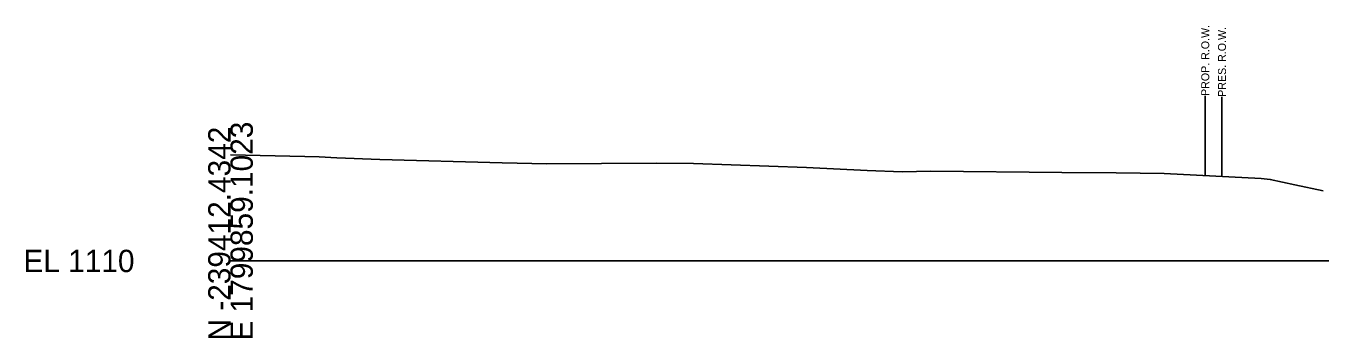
# Model space of a CAD drawing. Extents: x 214513 to 217151, y 214739 to 216780.
# Drawn here: x 214722.7 to 214885.1, y 215238.7 to 215277.9 of the extents above; entities that cross this region are included whole.
import ezdxf

# ---------------------------------------------------------------- set-up
doc = ezdxf.new("R2010")
doc.units = 0
for name, color, linetype in [('DESIGN - ROW - Right-of-Way Linework', 7, 'Continuous'), ('DESIGN - TRANSPORTATION - Text', 7, 'Continuous'), ('Section', 7, 'Continuous'), ('SURVEY - DTM GRAPHICS - Triangles', 7, 'Continuous'), ('SURVEY - PROPERTY - ROW Lines', 7, 'Continuous'), ('XSCell', 7, 'Continuous')]:
    doc.layers.add(name, color=color, linetype=linetype)

msp = doc.modelspace()

# ---------------------------------------------------------------- linework, layer by layer
at = {"layer": 'DESIGN - ROW - Right-of-Way Linework'}
msp.add_lwpolyline([(214870.72, 215269.07), (214870.72, 215259.07)], dxfattribs=at)
at = {"layer": 'SURVEY - DTM GRAPHICS - Triangles'}
msp.add_lwpolyline([(214748.36, 215261.66), (214757.7, 215261.48), (214759.5, 215261.43), (214761.71, 215261.29), (214767.1, 215261.11), (214782.47, 215260.69), (214788.08, 215260.54), (214801.81, 215260.62), (214806.46, 215260.57), (214820.67, 215260.1), (214828.26, 215259.7), (214832.66, 215259.53), (214836.28, 215259.64), (214852.71, 215259.47), (214859.52, 215259.4), (214865.55, 215259.34), (214877.74, 215258.71), (214878.88, 215258.6), (214881.98, 215257.92), (214885.51, 215257.15)], dxfattribs=at)
at = {"layer": 'SURVEY - PROPERTY - ROW Lines'}
msp.add_lwpolyline([(214872.82, 215268.96), (214872.82, 215258.96)], dxfattribs=at)
at = {"layer": 'XSCell'}
msp.add_line((214748.36, 215248.36), (214898.36, 215248.36), dxfattribs=at)

# ---------------------------------------------------------------- texts
at = {"layer": 'DESIGN - TRANSPORTATION - Text'}
for s, p in [('PROP. R.O.W.', (214871.22, 215269.07)), ('PRES. R.O.W.', (214873.32, 215268.96))]:
    msp.add_text(s, height=1, rotation=90, dxfattribs=at).set_placement(p)
at = {"layer": 'Section'}
msp.add_text('-', height=0.0001, dxfattribs=at).set_placement((214748.36, 215248.36))
at = {"layer": 'XSCell'}
for s, p in [('N -239412.4342', (214748.36, 215238.36)), ('E 1799859.1023', (214751.16, 215238.36))]:
    msp.add_text(s, height=2.8, rotation=90, dxfattribs=at).set_placement(p)
msp.add_text('EL 1110', height=2.8, dxfattribs=at).set_placement((214722.36, 215246.96))

doc.saveas('drawing.dxf')
